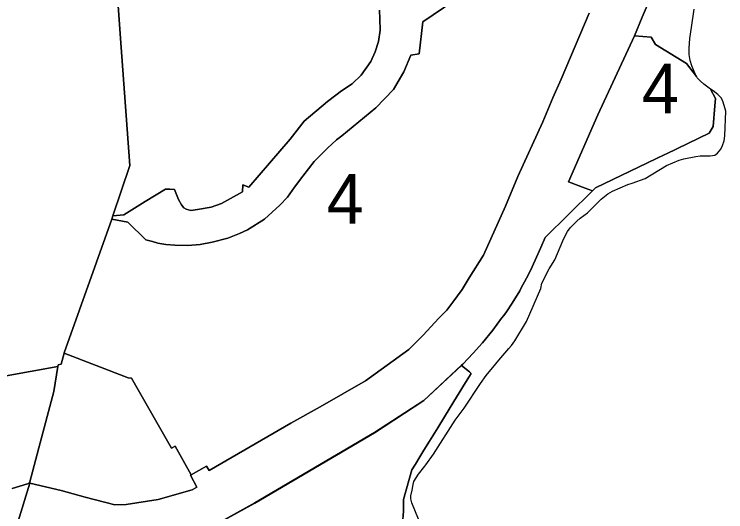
# Model space of a CAD drawing. Extents: x 598968 to 613553, y 4409678 to 4430833.
# Drawn here: x 610513.9 to 610685.8, y 4416279.7 to 4416399.9 of the extents above; entities that cross this region are included whole.
import ezdxf

# ---------------------------------------------------------------- set-up
doc = ezdxf.new("R2010")
doc.units = 0
for name, color, linetype in [('1', 7, 'Continuous'), ('4e. Sector de consolidació - ANNEX III A', 7, 'Continuous'), ('Sòl Rústic Protegit', 7, 'Continuous'), ('ZONA 4. CASES UNIFAMILIRAS AÏLLADES EN PARCEL.LES', 7, 'Continuous')]:
    doc.layers.add(name, color=color, linetype=linetype)

msp = doc.modelspace()

# ---------------------------------------------------------------- linework, layer by layer
at = {"layer": '1'}
for points in [[(610602.133, 4416400.8422), (610602.283, 4416398.7922), (610602.3363, 4416396.0746), (610601.8862, 4416393.2989), (610601.1227, 4416390.7904), (610600.0347, 4416388.4459), (610597.7172, 4416385.1475), (610595.5259, 4416383.0668), (610592.957, 4416381.3973), (610591.6205, 4416380.3414), (610589.638, 4416378.7939), (610584.0013, 4416374.0405), (610580.6062, 4416369.7114), (610570.6, 4416358.1074), (610569.1454, 4416358.6802), (610569.0748, 4416356.9655), (610563.9609, 4416354.2014), (610561.5296, 4416353.3079), (610558.2036, 4416352.7052), (610556.5834, 4416352.4982), (610555.4376, 4416352.8332), (610554.9066, 4416353.1682), (610554.2918, 4416353.8663), (610553.6211, 4416355.1784), (610552.643, 4416357.5794), (610551.4973, 4416357.6631), (610550.4353, 4416357.6073), (610545.517, 4416354.6757), (610540.431, 4416351.4369), (610537.7478, 4416351.1966), (610537.737, 4416351.1627), (610537.5065, 4416350.4183), (610541.3986, 4416349.7029), (610545.7006, 4416345.3737), (610547.2948, 4416344.9698), (610548.5714, 4416344.5654), (610550.533, 4416344.2855), (610552.6814, 4416344.13), (610555.8933, 4416344.006), (610558.8201, 4416344.2859), (610561.7336, 4416344.8353), (610565.5136, 4416345.8454), (610568.3436, 4416346.9454), (610570.3035, 4416347.8354), (610574.4134, 4416350.3555), (610578.0738, 4416353.7553), (610579.9734, 4416355.7055), (610581.6583, 4416358.1266), (610583.6633, 4416360.7555), (610586.3599, 4416364.3481), (610589.5729, 4416367.536), (610591.7525, 4416369.558), (610593.0602, 4416370.5535), (610601.273, 4416377.2956), (610605.553, 4416381.6955), (610608.0629, 4416385.9856), (610609.7671, 4416389.9714), (610611.7285, 4416390.3562), (610612.604, 4416398.0546), (610630.0997, 4416409.9695)], [(610558.8278, 4416274.5687), (610572.0217, 4416281.8667), (610600.9732, 4416298.8467), (610612.9084, 4416306.6162), (610621.9897, 4416315.0937), (610622.3405, 4416315.3883), (610624.8029, 4416318.0169), (610627.0379, 4416320.5412), (610629.5328, 4416323.6169), (610631.6728, 4416326.4569), (610632.1918, 4416327.1474), (610632.8227, 4416328.0269), (610634.2127, 4416330.1268), (610636.0427, 4416333.0869), (610636.3327, 4416333.6169), (610637.6827, 4416336.1068), (610638.638, 4416338.0104), (610639.8048, 4416340.503), (610641.1676, 4416343.5538), (610642.1946, 4416345.9559), (610653.6115, 4416357.217), (610651.866, 4416357.8606), (610651.8224, 4416357.8767), (610647.8214, 4416359.452), (610654.9231, 4416375.5774), (610663.7621, 4416394.7133), (610665.6539, 4416399.1727), (610667.6598, 4416403.911)], [(610667.6598, 4416403.911), (610665.6539, 4416399.1727), (610663.7621, 4416394.7133), (610667.8321, 4416394.3834), (610668.8221, 4416392.5735), (610676.3135, 4416388.0185), (610678.7461, 4416384.8847), (610678.414, 4416385.5176), (610678.004, 4416386.4576), (610677.624, 4416387.4575), (610677.254, 4416388.7174), (610677.014, 4416390.1374), (610676.974, 4416391.2974), (610677.0031, 4416391.6756), (610677.0038, 4416391.685), (610677.1839, 4416394.0273), (610677.5652, 4416396.7033), (610678.1938, 4416401.1172)], [(610652.8009, 4416400.1262), (610646.0374, 4416384.2133), (610644.0675, 4416379.726), (610641.6206, 4416373.882), (610635.626, 4416360.7069), (610632.5925, 4416353.543), (610627.2689, 4416341.6747), (610623.8129, 4416336.2366), (610622.1389, 4416333.3824), (610619.8932, 4416330.3121), (610618.4354, 4416328.3833), (610616.5049, 4416326.4939), (610612.7226, 4416322.3608), (610609.2436, 4416318.9157), (610598.8029, 4416311.3579), (610587.8672, 4416305.0365), (610580.736, 4416301.1002), (610561.0312, 4416289.7161), (610560.4009, 4416290.7395), (610556.655, 4416288.6642), (610556.6412, 4416288.6558), (610556.4933, 4416288.5668), (610558.0296, 4416285.6657), (610558.0163, 4416285.658), (610556.9039, 4416285.0261), (610548.6977, 4416282.7237), (610540.9255, 4416281.4953), (610538.2287, 4416281.4365), (610531.0655, 4416283.2516), (610525.2742, 4416284.8656), (610517.6725, 4416286.6541), (610517.6631, 4416286.6232), (610514.8606, 4416277.4444)], [(610611.6162, 4416277.9482), (610610.0062, 4416281.8481), (610609.7362, 4416282.818), (610609.7062, 4416283.588), (610610.0462, 4416284.978), (610610.2662, 4416286.278), (610610.4761, 4416287.0279), (610611.5961, 4416288.7779), (610613.1361, 4416290.7179), (610613.3661, 4416291.0479), (610615.1961, 4416293.6079), (610620.4559, 4416301.8279), (610622.6558, 4416304.7479), (610626.6057, 4416310.7278), (610627.9356, 4416312.6278), (610630.2555, 4416315.4878), (610630.9655, 4416316.3578), (610633.4455, 4416319.1378), (610634.0254, 4416319.8978), (610634.8754, 4416321.0079), (610637.6953, 4416325.6978), (610641.1151, 4416333.6477), (610641.3951, 4416334.9076), (610643.1251, 4416338.4076), (610644.565, 4416340.6077), (610646.435, 4416345.1576), (610647.2249, 4416346.6676), (610647.6149, 4416347.4176), (610648.2549, 4416348.2776), (610649.8448, 4416349.9076), (610649.8748, 4416349.9376), (610650.6548, 4416350.6376), (610652.4548, 4416351.9376), (610655.6946, 4416355.1876), (610657.3346, 4416356.4976), (610658.4546, 4416357.1777), (610662.1644, 4416358.7778), (610663.1944, 4416359.0778), (610666.3944, 4416360.2378), (610671.5042, 4416363.338), (610674.5741, 4416364.628), (610675.6841, 4416364.968), (610678.584, 4416365.5682), (610679.654, 4416365.7182), (610682.104, 4416365.7082), (610683.1939, 4416365.8884), (610683.8639, 4416366.3583), (610684.6138, 4416367.3284), (610685.0738, 4416368.2183), (610685.4438, 4416369.3183), (610685.6238, 4416370.5582), (610685.8338, 4416376.4481), (610685.2338, 4416378.648), (610684.7838, 4416379.628), (610684.2483, 4416380.2021), (610683.9538, 4416380.5179), (610682.7487, 4416381.3969), (610682.1807, 4416381.8112), (610683.3532, 4416379.5747), (610683.2137, 4416377.8068), (610682.8153, 4416372.7584), (610681.8381, 4416371.2), (610671.4982, 4416366.2106), (610671.1002, 4416366.0516), (610654.3965, 4416357.9912), (610653.6115, 4416357.217), (610642.1946, 4416345.9559), (610641.1676, 4416343.5538), (610639.8048, 4416340.503), (610638.638, 4416338.0104), (610637.6827, 4416336.1068), (610636.3327, 4416333.6169), (610636.0427, 4416333.0869), (610634.2127, 4416330.1268), (610632.8227, 4416328.0269), (610632.1918, 4416327.1474), (610631.6728, 4416326.4569), (610629.5328, 4416323.6169), (610627.0379, 4416320.5412), (610624.8029, 4416318.0169), (610622.3405, 4416315.3883), (610621.9897, 4416315.0937), (610612.9084, 4416306.6162), (610600.9732, 4416298.8467), (610572.0217, 4416281.8667), (610558.8278, 4416274.5687)], [(610558.8278, 4416274.5357), (610572.0217, 4416281.8336), (610600.9732, 4416298.8137), (610612.9084, 4416306.5832), (610621.9897, 4416315.0607), (610623.9273, 4416313.5323), (610624.2829, 4416313.1439), (610622.949, 4416310.9734), (610619.2228, 4416304.9105), (610616.2223, 4416300.0284), (610614.2222, 4416296.7739), (610612.8814, 4416294.5923), (610611.9218, 4416293.031), (610610.8256, 4416291.2473), (610609.9631, 4416289.8439), (610607.9332, 4416282.704), (610607.9632, 4416279.8741), (610607.0032, 4416267.5942)], [(610513.2076, 4416276.6586), (610514.8346, 4416277.3588), (610514.8462, 4416277.3968), (610514.8606, 4416277.4444), (610517.6631, 4416286.6232), (610517.5756, 4416286.6438), (610517.4237, 4416286.6047), (610517.0892, 4416286.5009), (610513.3724, 4416285.3476)]]:
    msp.add_lwpolyline(points, dxfattribs=at)
msp.add_lwpolyline([(610556.6412, 4416288.6558), (610552.7623, 4416295.5791), (610551.9489, 4416295.0949), (610542.2232, 4416311.9895), (610541.4237, 4416312.0825), (610526.0085, 4416318.0627), (610525.2746, 4416315.3359), (610524.5546, 4416315.2038), (610524.4123, 4416314.803), (610523.5101, 4416308.7749), (610519.8413, 4416295.1335), (610517.559, 4416286.6477), (610517.5756, 4416286.6438), (610517.6631, 4416286.6232), (610517.6725, 4416286.6541), (610525.2742, 4416284.8656), (610531.0655, 4416283.2516), (610538.2287, 4416281.4365), (610540.9255, 4416281.4953), (610548.6977, 4416282.7237), (610556.9039, 4416285.0261), (610558.0163, 4416285.658), (610558.0296, 4416285.6657), (610556.4933, 4416288.5668)], close=True, dxfattribs=at)
at = {"layer": '4e. Sector de consolidació - ANNEX III A'}
msp.add_lwpolyline([(610513.3724, 4416285.3476), (610517.0892, 4416286.5009), (610517.4237, 4416286.6047), (610517.5756, 4416286.6438), (610517.559, 4416286.6477), (610519.8413, 4416295.1335), (610523.5101, 4416308.7749), (610524.4123, 4416314.803), (610470.0047, 4416305.0173)], dxfattribs=at)
at = {"layer": 'Sòl Rústic Protegit'}
msp.add_lwpolyline([(610470.0047, 4416305.0173), (610524.4123, 4416314.803), (610524.5546, 4416315.2038), (610525.2746, 4416315.3359), (610526.0085, 4416318.0627), (610525.982, 4416318.0731), (610537.5065, 4416350.3853), (610537.5065, 4416350.4183), (610537.737, 4416351.1627), (610537.7478, 4416351.1966), (610541.8238, 4416363.3317), (610539.5325, 4416395.1497), (610536.5067, 4416437.1643), (610536.1332, 4416442.3518), (610531.4732, 4416507.0595), (610527.9336, 4416552.7288), (610527.6336, 4416557.9288), (610526.9435, 4416569.9586), (610528.7534, 4416607.0081)], dxfattribs=at)
at = {"layer": 'ZONA 4. CASES UNIFAMILIRAS AÏLLADES EN PARCEL.LES'}
for points in [[(610536.5067, 4416437.1643), (610539.5325, 4416395.1497), (610541.8238, 4416363.3317), (610537.7478, 4416351.1966), (610540.431, 4416351.4369), (610545.517, 4416354.6757), (610550.4353, 4416357.6073), (610551.4973, 4416357.6631), (610552.643, 4416357.5794), (610553.6211, 4416355.1784), (610554.2918, 4416353.8663), (610554.9066, 4416353.1682), (610555.4376, 4416352.8332), (610556.5834, 4416352.4982), (610558.2036, 4416352.7052), (610561.5296, 4416353.3079), (610563.9609, 4416354.2014), (610569.0748, 4416356.9655), (610569.1454, 4416358.6802), (610570.6, 4416358.1074), (610580.6062, 4416369.7114), (610584.0013, 4416374.0405), (610589.638, 4416378.7939), (610591.6205, 4416380.3414), (610592.957, 4416381.3973), (610595.5259, 4416383.0668), (610597.7172, 4416385.1475), (610600.0347, 4416388.4459), (610601.1227, 4416390.7904), (610601.8862, 4416393.2989), (610602.3363, 4416396.0746), (610602.283, 4416398.7922), (610602.133, 4416400.8422)], [(610630.0997, 4416409.9695), (610612.604, 4416398.0546), (610611.7285, 4416390.3562), (610609.7671, 4416389.9714), (610608.0629, 4416385.9856), (610605.553, 4416381.6955), (610601.273, 4416377.2956), (610593.0602, 4416370.5535), (610591.7525, 4416369.558), (610589.5729, 4416367.536), (610586.3599, 4416364.3481), (610583.6633, 4416360.7555), (610581.6583, 4416358.1266), (610579.9734, 4416355.7055), (610578.0738, 4416353.7553), (610574.4134, 4416350.3555), (610570.3035, 4416347.8354), (610568.3436, 4416346.9454), (610565.5136, 4416345.8454), (610561.7336, 4416344.8353), (610558.8201, 4416344.2859), (610555.8933, 4416344.006), (610552.6814, 4416344.13), (610550.533, 4416344.2855), (610548.5714, 4416344.5654), (610547.2948, 4416344.9698), (610545.7006, 4416345.3737), (610541.3986, 4416349.7029), (610537.5065, 4416350.4183), (610537.5065, 4416350.3853), (610525.982, 4416318.0731), (610526.0085, 4416318.0627), (610541.4237, 4416312.0825), (610542.2232, 4416311.9895), (610551.9489, 4416295.0949), (610552.7623, 4416295.5791), (610556.6412, 4416288.6558), (610556.655, 4416288.6642), (610560.4009, 4416290.7395), (610561.0312, 4416289.7161), (610580.736, 4416301.1002), (610587.8672, 4416305.0365), (610598.8029, 4416311.3579), (610609.2436, 4416318.9157), (610612.7226, 4416322.3608), (610616.5049, 4416326.4939), (610618.4354, 4416328.3833), (610619.8932, 4416330.3121), (610622.1389, 4416333.3824), (610623.8129, 4416336.2366), (610627.2689, 4416341.6747), (610632.5925, 4416353.543), (610635.626, 4416360.7069), (610641.6206, 4416373.882), (610644.0675, 4416379.726), (610646.0374, 4416384.2133), (610652.8009, 4416400.1262)], [(610607.0032, 4416267.5942), (610607.9632, 4416279.8741), (610607.9332, 4416282.704), (610609.9631, 4416289.8439), (610610.8256, 4416291.2473), (610611.9218, 4416293.031), (610612.8814, 4416294.5923), (610614.2222, 4416296.7739), (610616.2223, 4416300.0284), (610619.2228, 4416304.9105), (610622.949, 4416310.9734), (610624.2829, 4416313.1439), (610623.9273, 4416313.5323), (610621.9897, 4416315.0607), (610612.9084, 4416306.5832), (610600.9732, 4416298.8137), (610572.0217, 4416281.8336), (610558.8278, 4416274.5357)]]:
    msp.add_lwpolyline(points, dxfattribs=at)
msp.add_lwpolyline([(610678.7461, 4416384.8847), (610676.3135, 4416388.0185), (610668.8221, 4416392.5735), (610667.8321, 4416394.3834), (610663.7621, 4416394.7133), (610654.9231, 4416375.5774), (610647.8214, 4416359.452), (610651.8224, 4416357.8767), (610651.866, 4416357.8606), (610653.6115, 4416357.217), (610654.3965, 4416357.9912), (610671.1002, 4416366.0516), (610671.4982, 4416366.2106), (610681.8381, 4416371.2), (610682.8153, 4416372.7584), (610683.2137, 4416377.8068), (610683.3532, 4416379.5747), (610682.1807, 4416381.8112), (610680.5539, 4416382.9978), (610679.7139, 4416383.7176), (610679.4086, 4416384.0308), (610678.9439, 4416384.5076)], close=True, dxfattribs=at)

# ---------------------------------------------------------------- texts
for p in [(610665.5873, 4416375.9652), (610589.3975, 4416349.3126)]:
    msp.add_text('4', height=12, dxfattribs=at).set_placement(p)

doc.saveas('drawing.dxf')
